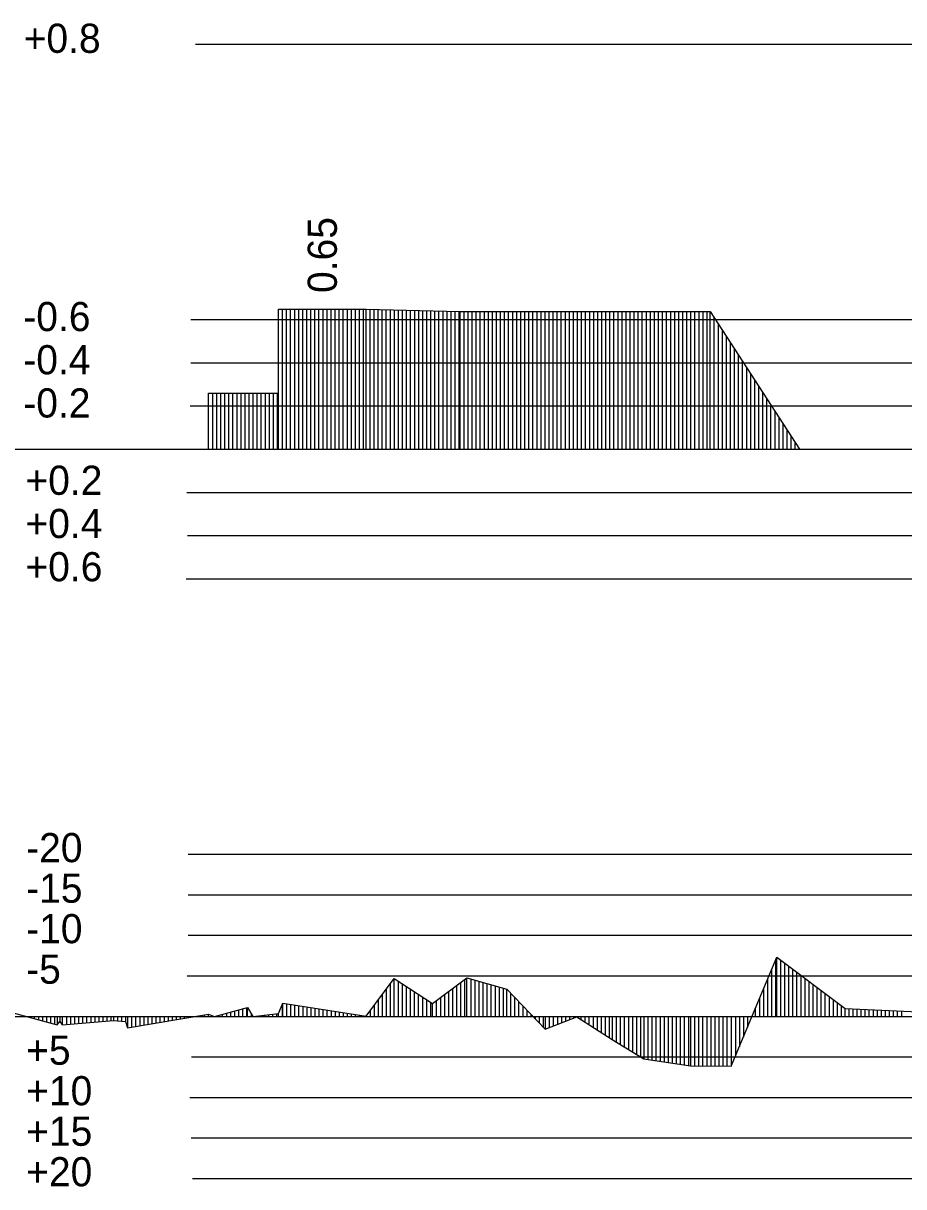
# Model space of a CAD drawing. Extents: x 2 to 10148, y 0 to 380.
# Drawn here: x 5134 to 5188.4, y 231.5 to 303.3 of the extents above; entities that cross this region are included whole.
import ezdxf

# ---------------------------------------------------------------- set-up
doc = ezdxf.new("R2010")
doc.units = 0
for name, color, linetype in [('POSUN_CARA', 7, 'Continuous'), ('POSUN_RASTR', 7, 'Continuous'), ('POSUN_TEXT', 7, 'Continuous'), ('ZRYCHL_CARA', 7, 'Continuous'), ('ZRYCHL_RASTR', 7, 'Continuous'), ('ZRYCHL_TEXT', 7, 'Continuous')]:
    doc.layers.add(name, color=color, linetype=linetype)

msp = doc.modelspace()

# ---------------------------------------------------------------- linework, layer by layer
at = {"layer": 'POSUN_CARA'}
for p, q in [((5177.72, 238.918), (5180.521, 245.645)), ((5180.521, 245.645), (5184.736, 242.481)), ((5180.521, 242), (5180.521, 245.645)), ((5180.22, 242), (5180.22, 244.922)), ((5180.47, 242), (5180.47, 245.522)), ((5180.771, 242), (5180.771, 245.457)), ((5181.021, 242), (5181.021, 245.269)), ((5181.271, 242), (5181.271, 245.082)), ((5181.521, 242), (5181.521, 244.894)), ((5155.19, 242.01), (5156.92, 244.338)), ((5156.92, 244.338), (5159.281, 242.79)), ((5156.92, 242), (5156.92, 244.338)), ((5157.17, 242), (5157.17, 244.174)), ((5159.281, 242.79), (5161.405, 244.372)), ((5161.281, 242), (5161.281, 244.28)), ((5161.405, 244.372), (5163.864, 243.675)), ((5161.405, 242), (5161.405, 244.372)), ((5161.655, 242), (5161.655, 244.301)), ((5161.905, 242), (5161.905, 244.23)), ((5162.155, 242), (5162.155, 244.159)), ((5179.97, 242), (5179.97, 244.322)), ((5181.771, 242), (5181.771, 244.706)), ((5182.021, 242), (5182.021, 244.519)), ((5182.271, 242), (5182.271, 244.331)), ((5182.521, 242), (5182.521, 244.144)), ((5156.44, 242), (5156.44, 243.693)), ((5156.69, 242), (5156.69, 244.029)), ((5157.42, 242), (5157.42, 244.01)), ((5157.67, 242), (5157.67, 243.847)), ((5157.92, 242), (5157.92, 243.683)), ((5158.17, 242), (5158.17, 243.519)), ((5160.281, 242), (5160.281, 243.535)), ((5160.531, 242), (5160.531, 243.721)), ((5160.781, 242), (5160.781, 243.907)), ((5161.031, 242), (5161.031, 244.093)), ((5162.405, 242), (5162.405, 244.088)), ((5162.655, 242), (5162.655, 244.018)), ((5162.905, 242), (5162.905, 243.947)), ((5163.155, 242), (5163.155, 243.876)), ((5163.405, 242), (5163.405, 243.805)), ((5163.655, 242), (5163.655, 243.734)), ((5163.864, 243.675), (5166.234, 241.215)), ((5163.864, 242), (5163.864, 243.675)), ((5164.114, 242), (5164.114, 243.415)), ((5179.72, 242), (5179.72, 243.721)), ((5182.771, 242), (5182.771, 243.956)), ((5183.021, 242), (5183.021, 243.768)), ((5183.271, 242), (5183.271, 243.581)), ((5183.521, 242), (5183.521, 243.393)), ((5149.772, 242.182), (5150.034, 242.813)), ((5150.022, 242), (5150.022, 242.782)), ((5150.034, 242.813), (5155.19, 242.01)), ((5150.034, 242), (5150.034, 242.813)), ((5150.284, 242), (5150.284, 242.774)), ((5150.534, 242), (5150.534, 242.736)), ((5150.784, 242), (5150.784, 242.697)), ((5155.69, 242), (5155.69, 242.683)), ((5155.94, 242), (5155.94, 243.02)), ((5156.19, 242), (5156.19, 243.356)), ((5158.42, 242), (5158.42, 243.355)), ((5158.67, 242), (5158.67, 243.191)), ((5158.92, 242), (5158.92, 243.027)), ((5159.17, 242), (5159.17, 242.863)), ((5159.281, 242), (5159.281, 242.79)), ((5159.531, 242), (5159.531, 242.977)), ((5159.781, 242), (5159.781, 243.163)), ((5160.031, 242), (5160.031, 243.349)), ((5164.364, 242), (5164.364, 243.156)), ((5164.614, 242), (5164.614, 242.896)), ((5179.47, 242), (5179.47, 243.121)), ((5183.771, 242), (5183.771, 243.205)), ((5184.021, 242), (5184.021, 243.018)), ((5184.271, 242), (5184.271, 242.83)), ((5132.949, 242.334), (5136.109, 241.477)), ((5134.199, 242), (5134.199, 241.995)), ((5134.449, 242), (5134.449, 241.927)), ((5134.699, 242), (5134.699, 241.859)), ((5134.949, 242), (5134.949, 241.792)), ((5135.199, 242), (5135.199, 241.724)), ((5135.449, 242), (5135.449, 241.656)), ((5135.699, 242), (5135.699, 241.588)), ((5135.949, 242), (5135.949, 241.521)), ((5136.109, 242), (5136.109, 241.477)), ((5136.268, 242), (5136.268, 241.688)), ((5136.429, 242), (5136.429, 241.472)), ((5136.679, 242), (5136.679, 241.494)), ((5136.929, 242), (5136.929, 241.516)), ((5137.179, 242), (5137.179, 241.538)), ((5137.429, 242), (5137.429, 241.56)), ((5137.679, 242), (5137.679, 241.582)), ((5137.929, 242), (5137.929, 241.604)), ((5138.179, 242), (5138.179, 241.626)), ((5138.429, 242), (5138.429, 241.648)), ((5138.679, 242), (5138.679, 241.67)), ((5138.929, 242), (5138.929, 241.692)), ((5139.179, 242), (5139.179, 241.714)), ((5139.429, 242), (5139.429, 241.736)), ((5139.591, 242), (5139.591, 241.75)), ((5139.841, 242), (5139.841, 241.731)), ((5140.091, 242), (5140.091, 241.711)), ((5140.336, 242), (5140.336, 241.692)), ((5140.455, 241.293), (5145.459, 242.126)), ((5140.455, 242), (5140.455, 241.293)), ((5140.705, 242), (5140.705, 241.334)), ((5140.955, 242), (5140.955, 241.376)), ((5141.205, 242), (5141.205, 241.418)), ((5141.455, 242), (5141.455, 241.459)), ((5141.705, 242), (5141.705, 241.501)), ((5141.955, 242), (5141.955, 241.543)), ((5142.205, 242), (5142.205, 241.584)), ((5142.455, 242), (5142.455, 241.626)), ((5142.705, 242), (5142.705, 241.667)), ((5142.955, 242), (5142.955, 241.709)), ((5143.205, 242), (5143.205, 241.751)), ((5143.455, 242), (5143.455, 241.792)), ((5143.705, 242), (5143.705, 241.834)), ((5143.955, 242), (5143.955, 241.876)), ((5144.205, 242), (5144.205, 241.917)), ((5144.455, 242), (5144.455, 241.959)), ((5144.705, 242), (5144.705, 242.001)), ((5144.955, 242), (5144.955, 242.042)), ((5145.205, 242), (5145.205, 242.084)), ((5145.455, 242), (5145.455, 242.125)), ((5145.459, 242.126), (5145.768, 242.011)), ((5145.459, 242), (5145.459, 242.126)), ((5145.709, 242), (5145.709, 242.033)), ((5145.825, 241.981), (5147.859, 242.539)), ((5145.825, 242), (5145.825, 241.981)), ((5146.075, 242), (5146.075, 242.05)), ((5146.325, 242), (5146.325, 242.119)), ((5146.575, 242), (5146.575, 242.187)), ((5146.825, 242), (5146.825, 242.256)), ((5147.075, 242), (5147.075, 242.324)), ((5147.325, 242), (5147.325, 242.393)), ((5147.575, 242), (5147.575, 242.461)), ((5147.825, 242), (5147.825, 242.53)), ((5147.859, 242.539), (5148.179, 241.999)), ((5147.859, 242), (5147.859, 242.539)), ((5148.109, 242), (5148.109, 242.116)), ((5148.179, 241.999), (5149.772, 242.182)), ((5148.179, 242), (5148.179, 241.999)), ((5148.429, 242), (5148.429, 242.027)), ((5148.679, 242), (5148.679, 242.056)), ((5148.929, 242), (5148.929, 242.085)), ((5149.179, 242), (5149.179, 242.113)), ((5149.429, 242), (5149.429, 242.142)), ((5149.679, 242), (5149.679, 242.171)), ((5149.772, 242), (5149.772, 242.182)), ((5151.034, 242), (5151.034, 242.658)), ((5151.284, 242), (5151.284, 242.619)), ((5151.534, 242), (5151.534, 242.58)), ((5151.784, 242), (5151.784, 242.541)), ((5152.034, 242), (5152.034, 242.502)), ((5152.284, 242), (5152.284, 242.463)), ((5152.534, 242), (5152.534, 242.424)), ((5152.784, 242), (5152.784, 242.385)), ((5153.034, 242), (5153.034, 242.346)), ((5153.284, 242), (5153.284, 242.307)), ((5153.534, 242), (5153.534, 242.268)), ((5153.784, 242), (5153.784, 242.229)), ((5154.034, 242), (5154.034, 242.19)), ((5154.284, 242), (5154.284, 242.151)), ((5154.534, 242), (5154.534, 242.112)), ((5154.784, 242), (5154.784, 242.073)), ((5155.034, 242), (5155.034, 242.034)), ((5155.19, 242), (5155.19, 242.01)), ((5155.44, 242), (5155.44, 242.346)), ((5164.864, 242), (5164.864, 242.637)), ((5165.114, 242), (5165.114, 242.378)), ((5165.364, 242), (5165.364, 242.118)), ((5165.614, 242), (5165.614, 241.859)), ((5165.864, 242), (5165.864, 241.599)), ((5166.114, 242), (5166.114, 241.34)), ((5166.234, 242), (5166.234, 241.215)), ((5166.234, 241.215), (5168.183, 241.979)), ((5166.484, 242), (5166.484, 241.313)), ((5166.734, 242), (5166.734, 241.411)), ((5166.984, 242), (5166.984, 241.509)), ((5167.234, 242), (5167.234, 241.607)), ((5167.484, 242), (5167.484, 241.705)), ((5167.734, 242), (5167.734, 241.804)), ((5167.984, 242), (5167.984, 241.902)), ((5168.183, 242), (5168.183, 241.979)), ((5168.183, 241.979), (5170.365, 240.563)), ((5168.433, 242), (5168.433, 241.817)), ((5168.683, 242), (5168.683, 241.655)), ((5168.933, 242), (5168.933, 241.493)), ((5169.183, 242), (5169.183, 241.33)), ((5169.433, 242), (5169.433, 241.168)), ((5169.683, 242), (5169.683, 241.006)), ((5169.933, 242), (5169.933, 240.843)), ((5170.183, 242), (5170.183, 240.681)), ((5170.365, 242), (5170.365, 240.563)), ((5170.615, 242), (5170.615, 240.41)), ((5170.865, 242), (5170.865, 240.258)), ((5171.115, 242), (5171.115, 240.105)), ((5171.365, 242), (5171.365, 239.953)), ((5171.615, 242), (5171.615, 239.8)), ((5171.865, 242), (5171.865, 239.648)), ((5172.115, 242), (5172.115, 239.495)), ((5172.318, 242), (5172.318, 239.372)), ((5172.568, 242), (5172.568, 239.336)), ((5172.818, 242), (5172.818, 239.299)), ((5173.068, 242), (5173.068, 239.263)), ((5173.318, 242), (5173.318, 239.227)), ((5173.568, 242), (5173.568, 239.191)), ((5173.818, 242), (5173.818, 239.155)), ((5174.068, 242), (5174.068, 239.118)), ((5174.318, 242), (5174.318, 239.082)), ((5174.568, 242), (5174.568, 239.046)), ((5174.818, 242), (5174.818, 239.01)), ((5175.068, 242), (5175.068, 238.973)), ((5175.201, 242), (5175.201, 238.954)), ((5175.451, 242), (5175.451, 238.951)), ((5175.701, 242), (5175.701, 238.947)), ((5175.951, 242), (5175.951, 238.943)), ((5176.201, 242), (5176.201, 238.94)), ((5176.451, 242), (5176.451, 238.936)), ((5176.701, 242), (5176.701, 238.933)), ((5176.951, 242), (5176.951, 238.929)), ((5177.201, 242), (5177.201, 238.925)), ((5177.451, 242), (5177.451, 238.922)), ((5177.701, 242), (5177.701, 238.918)), ((5177.72, 242), (5177.72, 238.918)), ((5177.97, 242), (5177.97, 239.518)), ((5178.22, 242), (5178.22, 240.119)), ((5178.47, 242), (5178.47, 240.719)), ((5178.72, 242), (5178.72, 241.32)), ((5178.97, 242), (5178.97, 241.92)), ((5179.22, 242), (5179.22, 242.52)), ((5184.521, 242), (5184.521, 242.642)), ((5184.736, 242.481), (5189.718, 242.268)), ((5184.736, 242), (5184.736, 242.481)), ((5184.986, 242), (5184.986, 242.47)), ((5185.236, 242), (5185.236, 242.46)), ((5185.486, 242), (5185.486, 242.449)), ((5185.736, 242), (5185.736, 242.438)), ((5185.986, 242), (5185.986, 242.428)), ((5186.236, 242), (5186.236, 242.417)), ((5186.486, 242), (5186.486, 242.406)), ((5186.736, 242), (5186.736, 242.396)), ((5186.986, 242), (5186.986, 242.385)), ((5187.236, 242), (5187.236, 242.374)), ((5187.486, 242), (5187.486, 242.364)), ((5187.736, 242), (5187.736, 242.353)), ((5187.986, 242), (5187.986, 242.342)), ((5188.236, 242), (5188.236, 242.332)), ((5136.109, 241.477), (5136.268, 241.688)), ((5136.268, 241.688), (5136.429, 241.472)), ((5136.429, 241.472), (5139.591, 241.75)), ((5139.591, 241.75), (5140.336, 241.692)), ((5140.336, 241.692), (5140.455, 241.293)), ((5170.365, 240.563), (5172.318, 239.372)), ((5172.318, 239.372), (5175.201, 238.954)), ((5175.201, 238.954), (5177.72, 238.918))]:
    msp.add_line(p, q, dxfattribs=at)
at = {"layer": 'POSUN_RASTR'}
for p, q in [((5144.201, 252), (5355.445, 252)), ((5144.201, 249.5), (5355.435, 249.5)), ((5144.201, 247), (5355.476, 247)), ((5144.125, 244.5), (5355.476, 244.5)), ((5128.6, 242), (5974.91, 242)), ((5144.393, 239.5), (5348, 239.5)), ((5144.292, 237), (5348, 237)), ((5144.38, 234.5), (5348, 234.5)), ((5144.468, 232), (5348, 232))]:
    msp.add_line(p, q, dxfattribs=at)
at = {"layer": 'ZRYCHL_CARA'}
for p, q in [((5149.771, 277), (5149.771, 285.637)), ((5149.771, 280.462), (5149.771, 285.637)), ((5149.771, 285.637), (5155.177, 285.637)), ((5150.021, 277), (5150.021, 285.637)), ((5150.271, 277), (5150.271, 285.637)), ((5150.521, 277), (5150.521, 285.637)), ((5150.771, 277), (5150.771, 285.637)), ((5151.021, 277), (5151.021, 285.637)), ((5151.271, 277), (5151.271, 285.637)), ((5151.521, 277), (5151.521, 285.637)), ((5151.771, 277), (5151.771, 285.637)), ((5152.021, 277), (5152.021, 285.637)), ((5152.271, 277), (5152.271, 285.637)), ((5152.521, 277), (5152.521, 285.637)), ((5152.771, 277), (5152.771, 285.637)), ((5153.021, 277), (5153.021, 285.637)), ((5153.271, 277), (5153.271, 285.637)), ((5153.521, 277), (5153.521, 285.637)), ((5153.771, 277), (5153.771, 285.637)), ((5154.021, 277), (5154.021, 285.637)), ((5154.271, 277), (5154.271, 285.637)), ((5154.521, 277), (5154.521, 285.637)), ((5154.771, 277), (5154.771, 285.637)), ((5155.021, 277), (5155.021, 285.637)), ((5155.177, 277), (5155.177, 285.637)), ((5155.177, 285.637), (5160.977, 285.488)), ((5155.427, 277), (5155.427, 285.631)), ((5155.677, 277), (5155.677, 285.624)), ((5155.927, 277), (5155.927, 285.618)), ((5156.177, 277), (5156.177, 285.611)), ((5156.427, 277), (5156.427, 285.605)), ((5156.677, 277), (5156.677, 285.598)), ((5156.927, 277), (5156.927, 285.592)), ((5157.177, 277), (5157.177, 285.586)), ((5157.427, 277), (5157.427, 285.579)), ((5157.677, 277), (5157.677, 285.573)), ((5157.927, 277), (5157.927, 285.566)), ((5158.177, 277), (5158.177, 285.56)), ((5158.427, 277), (5158.427, 285.553)), ((5158.677, 277), (5158.677, 285.547)), ((5158.927, 277), (5158.927, 285.541)), ((5159.177, 277), (5159.177, 285.534)), ((5159.427, 277), (5159.427, 285.528)), ((5159.677, 277), (5159.677, 285.521)), ((5159.927, 277), (5159.927, 285.515)), ((5160.177, 277), (5160.177, 285.509)), ((5160.427, 277), (5160.427, 285.502)), ((5160.677, 277), (5160.677, 285.496)), ((5160.927, 277), (5160.927, 285.489)), ((5160.977, 277), (5160.977, 285.488)), ((5160.977, 285.488), (5176.418, 285.488)), ((5161.227, 277), (5161.227, 285.488)), ((5161.477, 277), (5161.477, 285.488)), ((5161.727, 277), (5161.727, 285.488)), ((5161.977, 277), (5161.977, 285.488)), ((5162.227, 277), (5162.227, 285.488)), ((5162.477, 277), (5162.477, 285.488)), ((5162.727, 277), (5162.727, 285.488)), ((5162.977, 277), (5162.977, 285.488)), ((5163.227, 277), (5163.227, 285.488)), ((5163.477, 277), (5163.477, 285.488)), ((5163.727, 277), (5163.727, 285.488)), ((5163.977, 277), (5163.977, 285.488)), ((5164.227, 277), (5164.227, 285.488)), ((5164.477, 277), (5164.477, 285.488)), ((5164.727, 277), (5164.727, 285.488)), ((5164.977, 277), (5164.977, 285.488)), ((5165.227, 277), (5165.227, 285.488)), ((5165.477, 277), (5165.477, 285.488)), ((5165.727, 277), (5165.727, 285.488)), ((5165.977, 277), (5165.977, 285.488)), ((5166.227, 277), (5166.227, 285.488)), ((5166.477, 277), (5166.477, 285.488)), ((5166.727, 277), (5166.727, 285.488)), ((5166.977, 277), (5166.977, 285.488)), ((5167.227, 277), (5167.227, 285.488)), ((5167.477, 277), (5167.477, 285.488)), ((5167.727, 277), (5167.727, 285.488)), ((5167.977, 277), (5167.977, 285.488)), ((5168.227, 277), (5168.227, 285.488)), ((5168.477, 277), (5168.477, 285.488)), ((5168.727, 277), (5168.727, 285.488)), ((5168.977, 277), (5168.977, 285.488)), ((5169.227, 277), (5169.227, 285.488)), ((5169.477, 277), (5169.477, 285.488)), ((5169.727, 277), (5169.727, 285.488)), ((5169.977, 277), (5169.977, 285.488)), ((5170.227, 277), (5170.227, 285.488)), ((5170.477, 277), (5170.477, 285.488)), ((5170.727, 277), (5170.727, 285.488)), ((5170.977, 277), (5170.977, 285.488)), ((5171.227, 277), (5171.227, 285.488)), ((5171.477, 277), (5171.477, 285.488)), ((5171.727, 277), (5171.727, 285.488)), ((5171.977, 277), (5171.977, 285.488)), ((5172.227, 277), (5172.227, 285.488)), ((5172.477, 277), (5172.477, 285.488)), ((5172.727, 277), (5172.727, 285.488)), ((5172.977, 277), (5172.977, 285.488)), ((5173.227, 277), (5173.227, 285.488)), ((5173.477, 277), (5173.477, 285.488)), ((5173.727, 277), (5173.727, 285.488)), ((5173.977, 277), (5173.977, 285.488)), ((5174.227, 277), (5174.227, 285.488)), ((5174.477, 277), (5174.477, 285.488)), ((5174.727, 277), (5174.727, 285.488)), ((5174.977, 277), (5174.977, 285.488)), ((5175.227, 277), (5175.227, 285.488)), ((5175.477, 277), (5175.477, 285.488)), ((5175.727, 277), (5175.727, 285.488)), ((5175.977, 277), (5175.977, 285.488)), ((5176.227, 277), (5176.227, 285.488)), ((5176.418, 277), (5176.418, 285.488)), ((5176.418, 285.488), (5181.918, 277)), ((5176.668, 277), (5176.668, 285.102)), ((5176.918, 277), (5176.918, 284.716)), ((5177.168, 277), (5177.168, 284.331)), ((5177.418, 277), (5177.418, 283.945)), ((5177.668, 277), (5177.668, 283.559)), ((5177.918, 277), (5177.918, 283.173)), ((5178.168, 277), (5178.168, 282.787)), ((5178.418, 277), (5178.418, 282.401)), ((5178.668, 277), (5178.668, 282.016)), ((5178.918, 277), (5178.918, 281.63)), ((5179.168, 277), (5179.168, 281.244)), ((5179.418, 277), (5179.418, 280.858)), ((5145.459, 277), (5145.461, 280.462)), ((5145.461, 277), (5145.461, 280.462)), ((5145.461, 280.462), (5149.771, 280.462)), ((5145.711, 277), (5145.711, 280.462)), ((5145.961, 277), (5145.961, 280.462)), ((5146.211, 277), (5146.211, 280.462)), ((5146.461, 277), (5146.461, 280.462)), ((5146.711, 277), (5146.711, 280.462)), ((5146.961, 277), (5146.961, 280.462)), ((5147.211, 277), (5147.211, 280.462)), ((5147.461, 277), (5147.461, 280.462)), ((5147.711, 277), (5147.711, 280.462)), ((5147.961, 277), (5147.961, 280.462)), ((5148.211, 277), (5148.211, 280.462)), ((5148.461, 277), (5148.461, 280.462)), ((5148.711, 277), (5148.711, 280.462)), ((5148.961, 277), (5148.961, 280.462)), ((5149.211, 277), (5149.211, 280.462)), ((5149.461, 277), (5149.461, 280.462)), ((5149.711, 277), (5149.711, 280.462)), ((5179.668, 277), (5179.668, 280.472)), ((5179.918, 277), (5179.918, 280.087)), ((5180.168, 277), (5180.168, 279.701)), ((5180.418, 277), (5180.418, 279.315)), ((5180.668, 277), (5180.668, 278.929)), ((5180.918, 277), (5180.918, 278.543)), ((5181.168, 277), (5181.168, 278.157)), ((5181.418, 277), (5181.418, 277.772)), ((5181.668, 277), (5181.668, 277.386)), ((5128.6, 277), (5974.91, 277))]:
    msp.add_line(p, q, dxfattribs=at)
at = {"layer": 'ZRYCHL_RASTR'}
for p, q in [((5144.649, 302), (5348, 302)), ((5144.362, 285), (5355.697, 285)), ((5144.362, 282.333), (5355.777, 282.333)), ((5144.316, 279.667), (5355.807, 279.667)), ((5144.116, 274.333), (5348, 274.333)), ((5144.16, 271.667), (5348, 271.667)), ((5144.072, 269), (5348, 269))]:
    msp.add_line(p, q, dxfattribs=at)

# ---------------------------------------------------------------- texts
at = {"layer": 'POSUN_TEXT'}
for s, p in [('-20', (5134.196, 251.512)), ('-15', (5134.196, 249.012)), ('-10', (5134.196, 246.512)), ('-5', (5134.196, 244.012)), ('+5', (5134.196, 239.012)), ('+10', (5134.196, 236.512)), ('+15', (5134.196, 234.012)), ('+20', (5134.196, 231.512))]:
    msp.add_text(s, height=1.8, dxfattribs=at).set_placement(p)
at = {"layer": 'ZRYCHL_TEXT'}
for s, p in [('+0.8', (5134.043, 301.454)), ('-0.6', (5134.019, 284.284)), ('-0.4', (5134.019, 281.618)), ('-0.2', (5134.019, 278.951)), ('+0.2', (5134.152, 274.181)), ('+0.4', (5134.152, 271.514)), ('+0.6', (5134.152, 268.847))]:
    msp.add_text(s, height=1.8, dxfattribs=at).set_placement(p)
msp.add_text('0.65', height=1.8, rotation=90, dxfattribs=at).set_placement((5153.374, 286.637))

doc.saveas('drawing.dxf')
